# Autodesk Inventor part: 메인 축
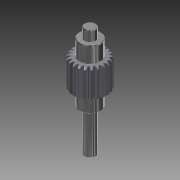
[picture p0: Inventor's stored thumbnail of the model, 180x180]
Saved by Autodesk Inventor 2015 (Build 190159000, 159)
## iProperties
Created: 2014-07
Part Number: 메인 축
Material: 강
Document SubType Name: Modeling
Designer: KYOUNG IL JANG
Categories: <?xml version="1.0" encoding="UTF-16"?> <MemberInstance><Categories><FamilyTemplate><FamilyTemplateParameter ValueType="xs:double" Id="1" ObjectReferenceKey="da
Density: 1 g/cm^3
Appearance: 강철
CustomPartVersion: 1
Company: 한국ATC센터
Author: KYOUNG IL JANG
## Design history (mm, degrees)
sketch "Sketch1"
  geometry: C1 r 12 at (0, 0)
  constraints: 1 centre point
  dimensions: "d0" = 24 diameter of C1 (= da_da)
extrude "Extrusion1" new body sketch "Sketch1" distance "d1" = 20 (= da_b); taper "d2" = 0 deg
workplane "Work Plane2"
feature "피치 지름" dims "d4" = 10, "d5" = 0
workplane "Work Plane8"
workplane "Work Plane9"
chamfer "모따기1" distance "d49" = 1; stored, may be unused: second distance "d50" = 2, angle "d51" = 45 deg
sketch "스케치3"
  geometry: C1 r 7.5 at (0, 0); 1 further point
  constraints: 1 centre point, 1 coincident
  dimensions: "d52" = 15 diameter of C1
extrude "돌출2" join sketch "스케치3" distance "d53" = 11; taper "d54" = 0 deg
sketch "스케치4"
  geometry: C1 r 4 at (0, 0); 1 further point
  constraints: 1 centre point, 1 coincident
  dimensions: "d55" = 8 diameter of C1
extrude "돌출3" join sketch "스케치4" distance "d56" = 7; taper "d57" = 0 deg
sketch "스케치5"
  geometry: C1 r 7.5 at (0, 0) reference; C2 r 7.5 at (0, 0) reference; 1 further point
extrude "돌출4" join sketch "스케치5" distance "d62" = 11; taper "d63" = 0 deg
sketch "스케치6"
  geometry: C1 r 4 at (0, 0); 1 further point
  constraints: 1 centre point, 1 coincident
  dimensions: "d64" = 8 diameter of C1
extrude "돌출5" join sketch "스케치6" distance "d65" = 30; taper "d66" = 0 deg
chamfer "모따기2" distance "d58" = 0.5; stored, may be unused: second distance "d59" = 2, angle "d60" = 45 deg
fillet "모깎기1" dims "d61" = 0.5
feature "스퍼 기어" dims "da_b" = 20, "da_d" = 22, "da_aw" = 31, "da_da" = 24, "da_df" = 19.5, "da_dw" = 22, angle "da_beta" = 0 deg, "da_lefttooth" = 0, "da_righttooth" = 0
body "Solid1"
sketch "Sketch2"
  geometry: C1 r 12 at (0, 0) reference; C2 r 11 at (0, 0)
  constraints: 1 centre point, 1 coincident
  dimensions: "d3" = 22 diameter of C2 (= da_dw)
body "Srf1"
node "투영된 루프1"
other parameters: "d16" = 31 (= da_aw), "d17" = 0, "d34" = 1.428 (computed from da_z), "d39" = 0, "d41" = 0, "d43" = 31 (= da_aw), "d46" = 31 (= da_aw), "d47" = 0, "d48" = 0
